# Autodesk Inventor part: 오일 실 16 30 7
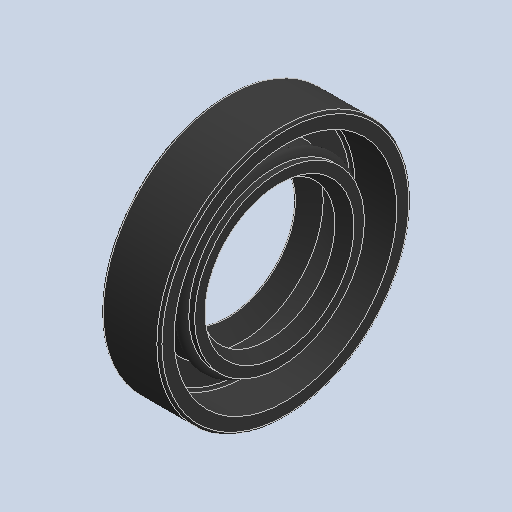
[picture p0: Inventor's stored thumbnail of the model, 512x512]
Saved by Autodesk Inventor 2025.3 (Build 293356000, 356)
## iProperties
Created: 2025-10
Part Number: 오일 실 16 30 7
Material: 고무
Description: 오일-실
Document SubType Name: Modeling
Designer: PC-04
Density: 0.93 g/cm^3
Appearance: 기본값
Author: jhkim
Sending System: Autodesk Inventor 2026
Preprocessor: ST-DEVELOPER v20.1
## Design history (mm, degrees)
feature "Solid1"
node "솔리드1"
